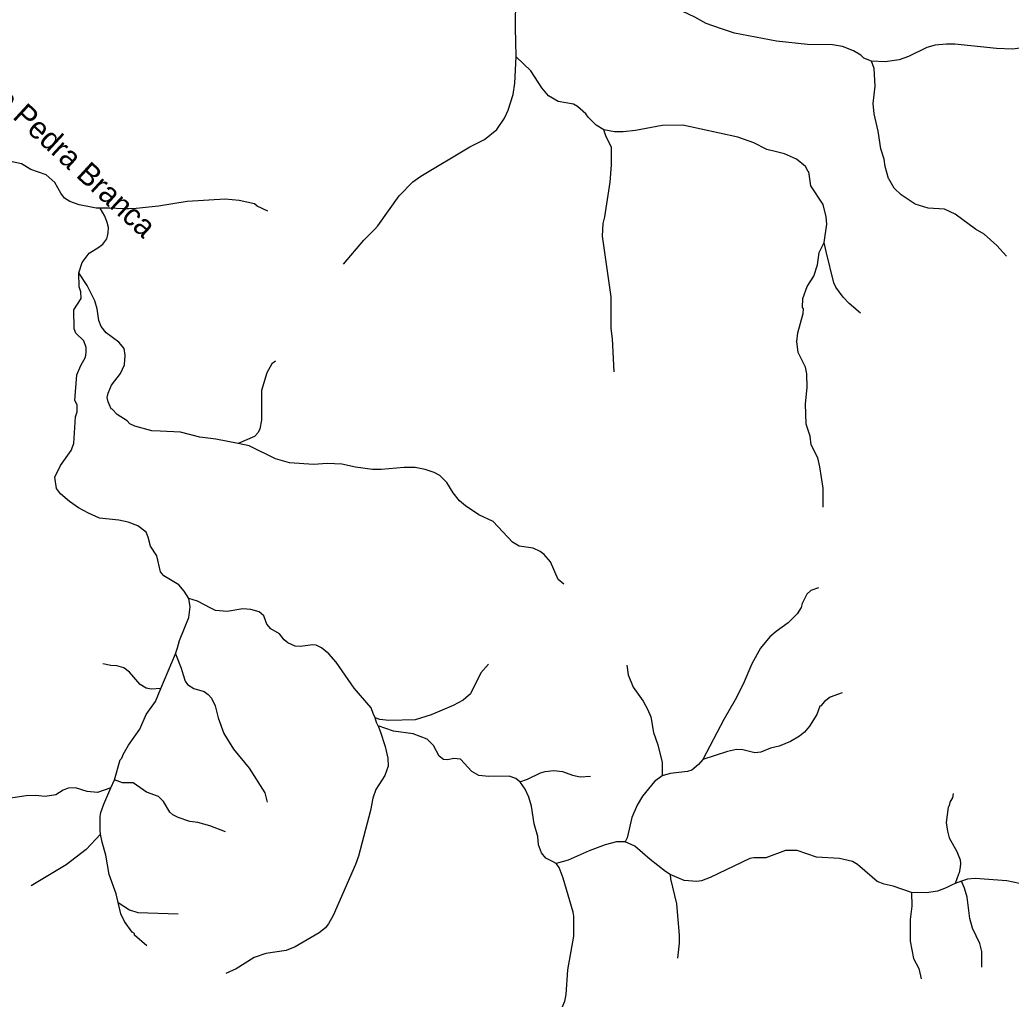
# Model space of a CAD drawing. Extents: x 396 to 422.2, y 7649.8 to 7677.6.
# Drawn here: x 415.262 to 418.881, y 7659.698 to 7663.274 of the extents above; entities that cross this region are included whole.
import ezdxf
from ezdxf.enums import TextEntityAlignment as Align

# ---------------------------------------------------------------- set-up
doc = ezdxf.new("R2010")
doc.units = 0
doc.header["$LTSCALE"] = 0.032
doc.layers.add('61', color=7, linetype='Continuous')
doc.layers.add('7', color=7, linetype='Continuous', lineweight=25)

msp = doc.modelspace()

# ---------------------------------------------------------------- linework, layer by layer
at = {"layer": '7'}
for p, q in [((415.7768, 7660.8323), (415.8298, 7660.9586)), ((415.5942, 7660.4698), (415.6072, 7660.4995)), ((418.6991, 7660.1291), (418.6756, 7660.1203))]:
    msp.add_line(p, q, dxfattribs=at)
for points in [[(417.0742, 7663.1392), (417.0725, 7663.1946), (417.071, 7663.2419), (417.0726, 7663.3573), (417.0916, 7663.4526), (417.1023, 7663.5567)], [(418.3705, 7663.1225), (418.3423, 7663.1336), (418.3314, 7663.1444), (418.3052, 7663.1608), (418.2654, 7663.1766), (418.2286, 7663.1821), (418.1374, 7663.1838), (418.0236, 7663.1957), (417.8713, 7663.2249), (417.8197, 7663.2426), (417.7677, 7663.2605), (417.7263, 7663.2836), (417.6795, 7663.3051), (417.6089, 7663.3233), (417.4768, 7663.3498), (417.3759, 7663.3823), (417.3642, 7663.387)], [(419.2429, 7663.1414), (419.2223, 7663.1414), (419.2182, 7663.1414), (419.2135, 7663.1414), (419.1976, 7663.1438), (419.1839, 7663.1501), (419.1744, 7663.1594), (419.1626, 7663.1808), (419.1509, 7663.1941), (419.1416, 7663.1999), (419.1166, 7663.2075), (419.0825, 7663.2125), (419.0584, 7663.2124), (418.9289, 7663.1725), (418.8861, 7663.1662), (418.8265, 7663.1695), (418.6753, 7663.1853), (418.6446, 7663.1853), (418.6035, 7663.1807), (418.5732, 7663.1724), (418.5063, 7663.1394), (418.4717, 7663.1276), (418.4202, 7663.1209), (418.3705, 7663.1225)], [(416.443, 7662.3821), (416.518, 7662.4689), (416.5561, 7662.508), (416.5689, 7662.5212), (416.6473, 7662.6316), (416.697, 7662.6821), (416.7254, 7662.7027), (416.905, 7662.8101), (416.9577, 7662.8372), (417.0029, 7662.8733), (417.0313, 7662.9145), (417.0444, 7662.9442), (417.0624, 7663.001), (417.0694, 7663.0427), (417.0742, 7663.1392)], [(417.3934, 7662.8724), (417.3654, 7662.8888), (417.3369, 7662.918), (417.3278, 7662.9309), (417.2978, 7662.9578), (417.2825, 7662.9654), (417.2265, 7662.9754), (417.1917, 7662.9962), (417.1678, 7663.0258), (417.1274, 7663.0875), (417.0742, 7663.1392)], [(418.8638, 7662.4114), (418.8286, 7662.45), (418.782, 7662.4913), (418.7503, 7662.5098), (418.676, 7662.5641), (418.6367, 7662.5824), (418.578, 7662.5857), (418.5299, 7662.601), (418.4795, 7662.6343), (418.4536, 7662.6592), (418.4342, 7662.6927), (418.4332, 7662.6945), (418.4206, 7662.738), (418.4171, 7662.7649), (418.4051, 7662.8032), (418.3948, 7662.867), (418.3805, 7662.9305), (418.3773, 7662.9684), (418.3845, 7663.031), (418.3806, 7663.0957), (418.3705, 7663.1225)], [(417.4315, 7661.9882), (417.4251, 7662.1091), (417.4204, 7662.1463), (417.4203, 7662.2154), (417.4203, 7662.2622), (417.3884, 7662.4843), (417.3917, 7662.5302), (417.3979, 7662.5546), (417.4171, 7662.681), (417.4219, 7662.7444), (417.4219, 7662.8086), (417.4027, 7662.8468), (417.3934, 7662.8724)], [(418.1982, 7662.4606), (418.2075, 7662.5278), (418.2058, 7662.5551), (418.1939, 7662.5998), (418.1493, 7662.6681), (418.1426, 7662.7183), (418.1394, 7662.7196), (418.1301, 7662.7379), (418.0971, 7662.7652), (418.053, 7662.7849), (418.0236, 7662.7921), (417.9885, 7662.8006), (417.9411, 7662.8245), (417.8833, 7662.8455), (417.6827, 7662.8887), (417.6062, 7662.8885), (417.5097, 7662.87), (417.4642, 7662.8648), (417.4326, 7662.8649), (417.3934, 7662.8724)], [(415.5549, 7662.5857), (415.5408, 7662.5866), (415.5225, 7662.5897), (415.4789, 7662.5984), (415.4446, 7662.6105), (415.4253, 7662.623), (415.4118, 7662.6406), (415.3897, 7662.68), (415.3588, 7662.7076), (415.3019, 7662.7269), (415.2679, 7662.7475), (415.188, 7662.7653), (415.1553, 7662.7822), (415.1022, 7662.819)], [(416.167, 7662.5754), (416.1286, 7662.5936), (416.1182, 7662.6016), (416.0627, 7662.6136), (416.0116, 7662.6192), (415.873, 7662.6105), (415.7686, 7662.5931), (415.6866, 7662.5848), (415.6599, 7662.584), (415.638, 7662.5833), (415.5905, 7662.5864), (415.5549, 7662.5857)], [(415.4772, 7662.3499), (415.4891, 7662.3874), (415.5146, 7662.4215), (415.5503, 7662.4432), (415.5647, 7662.4551), (415.5792, 7662.474), (415.5821, 7662.4841), (415.5849, 7662.4957), (415.5852, 7662.5159), (415.5812, 7662.534), (415.5718, 7662.5565), (415.5549, 7662.5857)], [(418.194, 7661.4947), (418.1939, 7661.5636), (418.1827, 7661.6414), (418.1747, 7661.6749), (418.1509, 7661.722), (418.1475, 7661.7533), (418.1324, 7661.7973), (418.1301, 7661.8719), (418.1365, 7661.931), (418.1349, 7661.9815), (418.1294, 7662.0052), (418.103, 7662.0587), (418.0983, 7662.0996), (418.1024, 7662.1316), (418.1214, 7662.2019), (418.1221, 7662.2191), (418.119, 7662.2231), (418.1205, 7662.2567), (418.1356, 7662.2998), (418.1598, 7662.3374), (418.1732, 7662.3799), (418.1796, 7662.4242), (418.1908, 7662.4457), (418.1982, 7662.4606)], [(418.3312, 7662.2034), (418.2891, 7662.2385), (418.2676, 7662.2608), (418.2403, 7662.2982), (418.2335, 7662.3141), (418.2052, 7662.4274), (418.1982, 7662.4606)], [(415.8792, 7661.161), (415.8624, 7661.1885), (415.8429, 7661.2107), (415.7874, 7661.2441), (415.7758, 7661.2591), (415.7616, 7661.3173), (415.7393, 7661.3528), (415.7307, 7661.3855), (415.7229, 7661.4039), (415.6927, 7661.4262), (415.6576, 7661.4397), (415.6232, 7661.4467), (415.5523, 7661.4549), (415.5124, 7661.4725), (415.4761, 7661.4927), (415.4428, 7661.5159), (415.4109, 7661.543), (415.3961, 7661.5632), (415.39, 7661.6047), (415.4106, 7661.6464), (415.4497, 7661.7021), (415.4592, 7661.7271), (415.4656, 7661.824), (415.4712, 7661.8424), (415.4712, 7661.8683), (415.4634, 7661.8842), (415.4705, 7661.9775), (415.4849, 7662.0115), (415.5017, 7662.042), (415.5047, 7662.0592), (415.5038, 7662.0772), (415.4951, 7662.102), (415.4665, 7662.1297), (415.4601, 7662.1458), (415.4586, 7662.2153), (415.4856, 7662.2565), (415.4848, 7662.2807), (415.4792, 7662.2994), (415.4772, 7662.3499)], [(416.0585, 7661.7266), (415.9769, 7661.7426), (415.9191, 7661.7507), (415.8484, 7661.768), (415.7747, 7661.7715), (415.7437, 7661.773), (415.6816, 7661.7901), (415.6639, 7661.799), (415.6541, 7661.8094), (415.6174, 7661.8325), (415.599, 7661.8524), (415.5955, 7661.8531), (415.5847, 7661.8787), (415.5814, 7661.8947), (415.5845, 7661.911), (415.5968, 7661.9403), (415.6293, 7661.9823), (415.6441, 7662.0139), (415.6468, 7662.0497), (415.6435, 7662.0742), (415.623, 7662.0973), (415.5771, 7662.1305), (415.5591, 7662.1536), (415.5509, 7662.1764), (415.5447, 7662.2184), (415.5357, 7662.2478), (415.5073, 7662.3038), (415.4772, 7662.3499)], [(416.1956, 7662.0274), (416.1824, 7662.0175), (416.1637, 7661.9847), (416.1444, 7661.9208), (416.1443, 7661.8117), (416.1384, 7661.781), (416.1318, 7661.7678), (416.1185, 7661.7521), (416.0585, 7661.7266)], [(417.2478, 7661.2132), (417.2274, 7661.2308), (417.199, 7661.2946), (417.1763, 7661.3216), (417.1611, 7661.3327), (417.1355, 7661.3444), (417.0851, 7661.3523), (417.0598, 7661.3666), (416.9892, 7661.4418), (416.9376, 7661.4669), (416.8887, 7661.4994), (416.8669, 7661.5179), (416.8439, 7661.547), (416.8212, 7661.585), (416.7946, 7661.6108), (416.7748, 7661.6208), (416.7422, 7661.6319), (416.7049, 7661.6389), (416.6647, 7661.6389), (416.5808, 7661.632), (416.5492, 7661.6319), (416.487, 7661.6406), (416.4369, 7661.6517), (416.384, 7661.6541), (416.3341, 7661.6509), (416.2468, 7661.6565), (416.1954, 7661.6716), (416.0989, 7661.7187), (416.0585, 7661.7266)], [(418.1777, 7661.1996), (418.1495, 7661.1909), (418.1346, 7661.1774), (418.1174, 7661.1426), (418.1141, 7661.1282), (418.0991, 7661.105), (418.0668, 7661.0725), (418.023, 7661.0413), (418.0001, 7661.0209), (417.9658, 7660.9794), (417.9341, 7660.9224), (417.9022, 7660.8489), (417.8733, 7660.7913), (417.8318, 7660.7195), (417.7549, 7660.5736)], [(415.8298, 7660.9586), (415.837, 7660.9809), (415.8454, 7661.0081), (415.8637, 7661.0533), (415.8795, 7661.0924), (415.8844, 7661.1311), (415.8792, 7661.161)], [(416.5594, 7660.7251), (416.5523, 7660.7414), (416.544, 7660.762), (416.4825, 7660.8344), (416.4172, 7660.9287), (416.3902, 7660.9593), (416.3633, 7660.9817), (416.3441, 7660.9905), (416.3298, 7660.9922), (416.2866, 7660.9859), (416.2668, 7660.987), (416.2399, 7660.9991), (416.2271, 7661.0101), (416.2099, 7661.0326), (416.1782, 7661.05), (416.1638, 7661.0671), (416.1522, 7661.0976), (416.1361, 7661.1127), (416.1053, 7661.1205), (416.0762, 7661.1238), (416.0187, 7661.1135), (415.9766, 7661.1172), (415.9598, 7661.1258), (415.9107, 7661.1509), (415.8792, 7661.161)], [(415.8298, 7660.9586), (415.8506, 7660.9069), (415.8582, 7660.8825), (415.8655, 7660.8588), (415.8744, 7660.8475), (415.8968, 7660.8321), (415.9348, 7660.8213), (415.9495, 7660.8113), (415.9611, 7660.7973), (415.9752, 7660.7692), (415.9856, 7660.7258), (416.0068, 7660.6678), (416.0425, 7660.6107), (416.0986, 7660.5418), (416.1563, 7660.4515), (416.1652, 7660.4173)], [(415.7768, 7660.8323), (415.7417, 7660.8304), (415.7234, 7660.8339), (415.7007, 7660.8474), (415.6619, 7660.8923), (415.6411, 7660.9076), (415.6156, 7660.9155), (415.5945, 7660.9164), (415.5647, 7660.9221)], [(416.973, 7660.9213), (416.9444, 7660.8904), (416.9071, 7660.8129), (416.8802, 7660.7905), (416.8439, 7660.771), (416.7639, 7660.7362), (416.7049, 7660.7179), (416.6088, 7660.7156), (416.5761, 7660.7195), (416.5594, 7660.7251)], [(417.4779, 7660.9181), (417.4828, 7660.883), (417.5011, 7660.8372), (417.537, 7660.7861), (417.5535, 7660.7577), (417.5656, 7660.7287), (417.575, 7660.6716), (417.5914, 7660.6272), (417.6069, 7660.5628), (417.607, 7660.5132)], [(415.6072, 7660.4995), (415.6281, 7660.5721), (415.634, 7660.5787), (415.6389, 7660.5922), (415.6586, 7660.6256), (415.6997, 7660.6837), (415.7234, 7660.7373), (415.7567, 7660.7848), (415.7768, 7660.8323)], [(418.2634, 7660.8168), (418.2194, 7660.8008), (418.1987, 7660.7848), (418.1862, 7660.7695), (418.1825, 7660.7684), (418.1715, 7660.7383), (418.1444, 7660.6953), (418.1259, 7660.6738), (418.1076, 7660.6583), (418.0753, 7660.6386), (418.0339, 7660.6225), (418.0019, 7660.6144), (417.9663, 7660.5996), (417.9444, 7660.5983), (417.9008, 7660.6086), (417.8785, 7660.6095), (417.8457, 7660.6026), (417.7549, 7660.5736)], [(416.5702, 7660.6959), (416.5638, 7660.708), (416.5594, 7660.7251)], [(416.5702, 7660.6959), (416.5761, 7660.6795), (416.5769, 7660.6773), (416.5957, 7660.621), (416.6052, 7660.5783), (416.6069, 7660.5488), (416.5941, 7660.5154), (416.561, 7660.4645), (416.5507, 7660.4326), (416.5417, 7660.3869), (416.4984, 7660.2202), (416.4876, 7660.1902), (416.4053, 7660.0036), (416.3892, 7659.9735), (416.3804, 7659.9624), (416.3779, 7659.9593), (416.3552, 7659.9405), (416.2669, 7659.8891), (416.234, 7659.8762), (416.1603, 7659.8653), (416.1175, 7659.8512), (416.0518, 7659.8088), (416.0144, 7659.7921)], [(417.0872, 7660.4923), (417.0721, 7660.5045), (417.0476, 7660.5126), (416.9745, 7660.5114), (416.9378, 7660.5146), (416.9125, 7660.5302), (416.8701, 7660.575), (416.8466, 7660.5776), (416.8226, 7660.572), (416.8084, 7660.5736), (416.7928, 7660.5856), (416.7717, 7660.6241), (416.7483, 7660.6476), (416.6975, 7660.6669), (416.6262, 7660.6768), (416.5702, 7660.6959)], [(417.7549, 7660.5736), (417.7392, 7660.5549), (417.7145, 7660.5349), (417.6992, 7660.5296), (417.6357, 7660.5225), (417.607, 7660.5132)], [(417.0872, 7660.4923), (417.1154, 7660.5016), (417.1628, 7660.5246), (417.1795, 7660.5296), (417.2111, 7660.5328), (417.2433, 7660.5296), (417.2789, 7660.5163), (417.3074, 7660.5099), (417.3447, 7660.5122)], [(417.607, 7660.5132), (417.5789, 7660.4928), (417.5352, 7660.4395), (417.5151, 7660.4066), (417.4961, 7660.3622), (417.4795, 7660.2879), (417.4713, 7660.2734)], [(415.5942, 7660.4698), (415.5451, 7660.4531), (415.5082, 7660.4566), (415.4657, 7660.4706), (415.4386, 7660.4686), (415.4203, 7660.4618), (415.3938, 7660.4442), (415.354, 7660.4388), (415.3189, 7660.4419), (415.2855, 7660.4411), (415.1963, 7660.4278), (415.1673, 7660.4191), (415.126, 7660.4006)], [(416.0128, 7660.3096), (415.9553, 7660.3309), (415.9115, 7660.343), (415.8821, 7660.3472), (415.8404, 7660.3611), (415.8211, 7660.3711), (415.8093, 7660.3809), (415.787, 7660.4197), (415.7679, 7660.4387), (415.7242, 7660.4543), (415.6763, 7660.4886), (415.6716, 7660.4886), (415.6367, 7660.4883), (415.6072, 7660.4995)], [(417.2197, 7660.194), (417.2086, 7660.1993), (417.1823, 7660.2134), (417.1659, 7660.2333), (417.1557, 7660.2613), (417.1524, 7660.2923), (417.1398, 7660.3391), (417.1302, 7660.4029), (417.1195, 7660.4363), (417.1063, 7660.4655), (417.09, 7660.49), (417.0872, 7660.4923)], [(415.5571, 7660.3009), (415.5548, 7660.3142), (415.5552, 7660.3638), (415.5552, 7660.3652), (415.5577, 7660.3805), (415.5683, 7660.4109), (415.5942, 7660.4698)], [(418.6693, 7660.4492), (418.6662, 7660.4331), (418.6582, 7660.4197), (418.6532, 7660.4015), (418.6502, 7660.3994), (418.6439, 7660.3432), (418.6479, 7660.3124), (418.6548, 7660.2878), (418.6822, 7660.2375), (418.6947, 7660.2076), (418.6962, 7660.1937), (418.6947, 7660.18), (418.6902, 7660.1599), (418.6889, 7660.1544), (418.6756, 7660.1203)], [(415.5571, 7660.3009), (415.5045, 7660.2447), (415.4309, 7660.1893), (415.3031, 7660.1127)], [(415.6208, 7660.051), (415.6133, 7660.0836), (415.5877, 7660.1532), (415.5758, 7660.2247), (415.5622, 7660.272), (415.5571, 7660.3009)], [(417.3984, 7660.2618), (417.3403, 7660.24), (417.2636, 7660.2065), (417.2197, 7660.194)], [(417.4713, 7660.2734), (417.4402, 7660.2725), (417.3984, 7660.2618)], [(417.6359, 7660.153), (417.619, 7660.1647), (417.5627, 7660.2083), (417.5075, 7660.2567), (417.4713, 7660.2734)], [(418.5165, 7660.0879), (418.4499, 7660.1109), (418.4171, 7660.1179), (418.3915, 7660.1275), (418.328, 7660.1827), (418.3194, 7660.1897), (418.3014, 7660.2007), (418.2545, 7660.2122), (418.1697, 7660.2164), (418.0991, 7660.241), (418.0567, 7660.2409), (417.9847, 7660.2146), (417.9416, 7660.2146), (417.9268, 7660.212), (417.7815, 7660.1423), (417.7497, 7660.1304), (417.7334, 7660.1278), (417.6865, 7660.1314), (417.6359, 7660.153)], [(417.1425, 7659.5505), (417.1566, 7659.5771), (417.184, 7659.6037), (417.2048, 7659.6171), (417.2317, 7659.6448), (417.2514, 7659.6915), (417.2561, 7659.715), (417.2624, 7659.8055), (417.2847, 7659.928), (417.2847, 7659.9989), (417.2843, 7660.002), (417.2824, 7660.0158), (417.2455, 7660.1397), (417.2304, 7660.1795), (417.2197, 7660.194)], [(417.6359, 7660.153), (417.6374, 7660.1383), (417.6595, 7660.0471), (417.6691, 7659.9323), (417.6691, 7659.9028), (417.6629, 7659.8479)], [(418.6756, 7660.1203), (418.6655, 7660.1158), (418.6438, 7660.105), (418.6121, 7660.0931), (418.5711, 7660.0863), (418.5165, 7660.0879)], [(419.2779, 7660.0152), (419.252, 7660.0226), (419.2356, 7660.0309), (419.2154, 7660.0446), (419.1995, 7660.0615), (419.1832, 7660.0733), (419.17, 7660.079), (419.1417, 7660.083), (419.1368, 7660.0818), (419.1123, 7660.0758), (419.0559, 7660.0483), (419.0395, 7660.0466), (419.0115, 7660.053), (418.9824, 7660.068), (418.9375, 7660.1068), (418.9112, 7660.1204), (418.8646, 7660.1308), (418.7494, 7660.1389), (418.7216, 7660.1367), (418.6991, 7660.1291)], [(418.7739, 7659.8154), (418.7729, 7659.8725), (418.7657, 7659.9012), (418.7389, 7659.9579), (418.7298, 7659.9925), (418.7202, 7660.0703), (418.7106, 7660.1041), (418.6991, 7660.1291)], [(418.5165, 7660.0879), (418.5177, 7660.0377), (418.5114, 7659.9896), (418.5115, 7659.9105), (418.5242, 7659.847), (418.5432, 7659.8103), (418.5521, 7659.7729)], [(415.7257, 7659.8927), (415.6806, 7659.9325), (415.6801, 7659.9378), (415.6723, 7659.9428), (415.6445, 7659.9824), (415.6302, 7660.0106), (415.6208, 7660.051)], [(415.6208, 7660.051), (415.6619, 7660.0245), (415.6927, 7660.0153), (415.8406, 7660.0098)]]:
    msp.add_lwpolyline(points, dxfattribs=at)

# ---------------------------------------------------------------- texts
at = {"layer": '61'}
msp.add_text('Córrego Pedra Branca', height=0.08, rotation=317.313, dxfattribs=at).set_placement((415.3196, 7662.836), align=Align.CENTER)

doc.saveas('drawing.dxf')
